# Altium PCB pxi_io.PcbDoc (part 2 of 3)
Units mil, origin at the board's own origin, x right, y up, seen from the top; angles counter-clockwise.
Board outline 6300 x 3935 mil, 2 copper layers (Top Layer, Bottom Layer); 257 components, 420 nets, 1532 pads, 239 vias.
Unrouted connection lines stored in the file: 158.
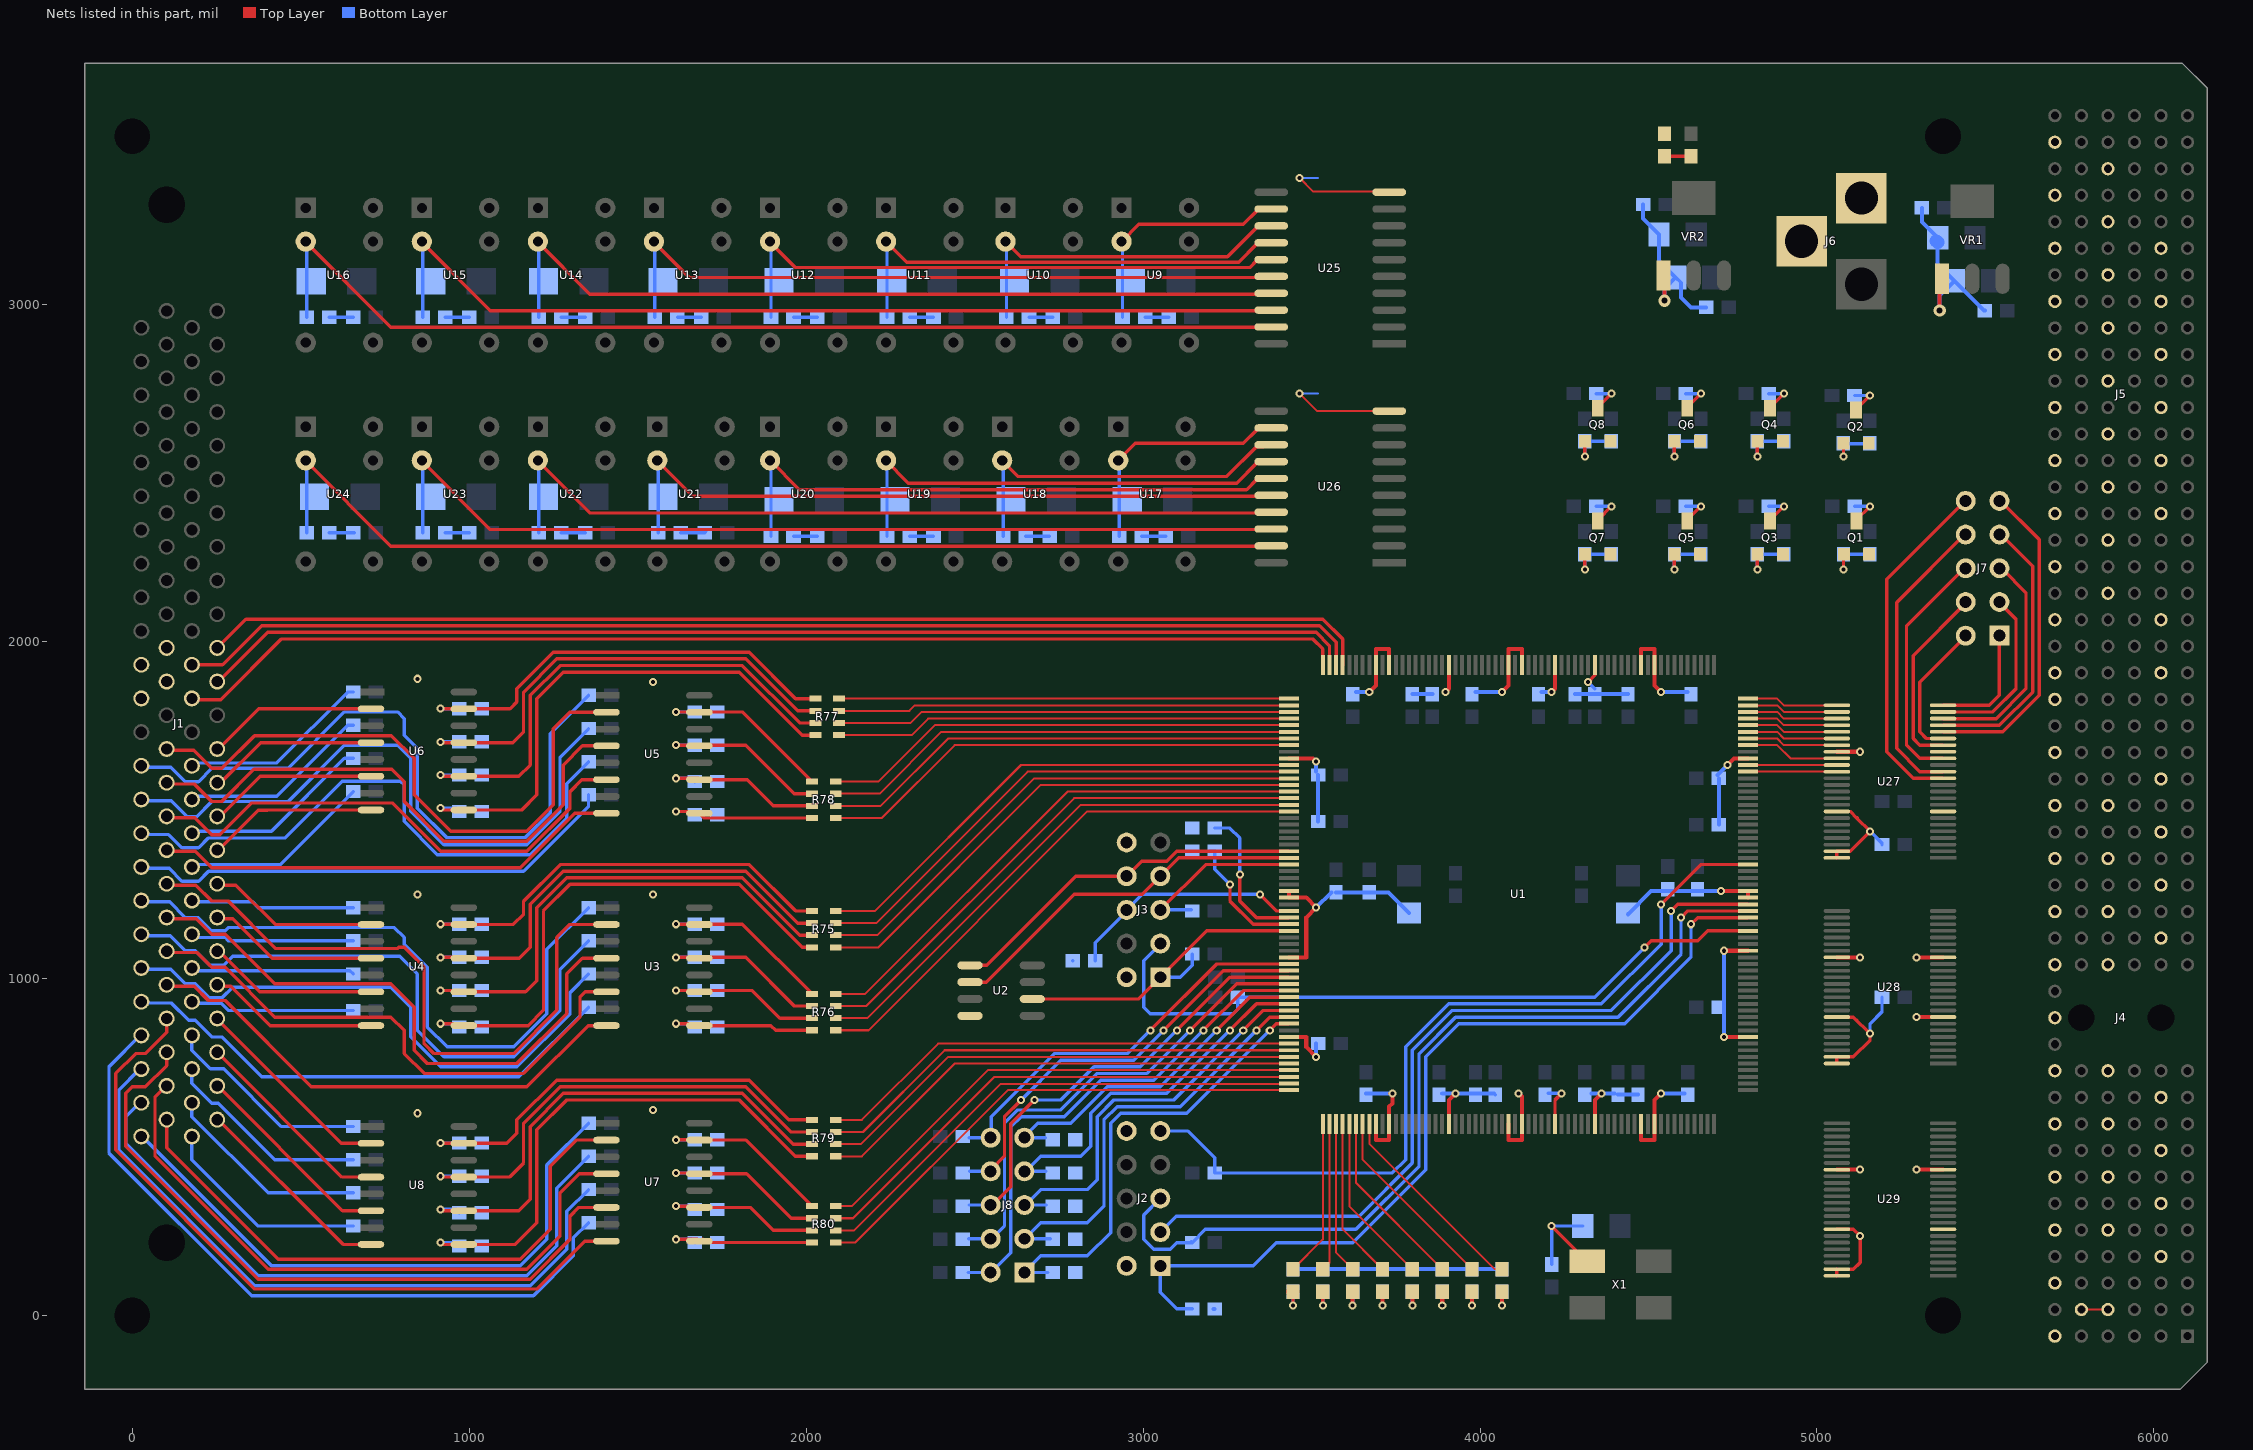
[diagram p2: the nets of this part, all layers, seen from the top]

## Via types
v1: diameter 24, hole 12, Top Layer to Bottom Layer, 232 vias
v2: diameter 36, hole 18, Top Layer to Bottom Layer, 6 vias
v3: diameter 24, hole 12, Top Layer to Bottom Layer, tented bottom, 1 vias

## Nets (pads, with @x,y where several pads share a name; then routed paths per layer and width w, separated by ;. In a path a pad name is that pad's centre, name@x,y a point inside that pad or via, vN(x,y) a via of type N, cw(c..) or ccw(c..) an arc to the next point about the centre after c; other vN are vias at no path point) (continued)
CONF_DONE: J3.3 R6.2 U1.145 | length 2131.5
  Top Layer w10: v1(4488.19,1092.52) 4507.87,1112.2 4645.67,1112.2 4675.2,1141.73 U1.145@4795.28,1141.73
  Bottom Layer w10: J3.3@3051.18,1102.36 3001.97,1053.15 3001.97,915.35 3021.65,895.67 3267.72,895.67 3281.5,909.45 R6.2@3281.5,944.88 4340.55,944.88 v1(4488.19,1092.52)
CTRL_RES1: J1.29 U1.238 | length 3532.9
  Top Layer w10: J1.29@177.17,1931.5 268.11,1931.5 383.86,2047.24 3523.62,2047.24 3572.83,1998.03 U1.238@3572.83,1931.1 U1.238@3572.83,1929.13
CTRL_RES2: J1.30 U1.237 | length 3478.9
  Top Layer w10: J1.30@252.17,1981.5 337.6,2066.93 3533.46,2066.93 3592.52,2007.87 U1.237@3592.52,1929.13
CTRL_V5: J1.27 U1.240 | length 3492.4
  Top Layer w10: J1.27@177.17,1827.56 262.6,1827.56 442.91,2007.87 3503.94,2007.87 3533.46,1978.35 U1.240@3533.46,1929.13
CTRL_V27: J1.28 U1.239 | length 3428.6
  Top Layer w10: J1.28@252.17,1877.56 402.17,2027.56 3513.78,2027.56 3553.15,1988.19 U1.239@3553.15,1938.98
DATA: J3.7 U1.25 U2.2 | length 1077.7
  Top Layer w10: U2.2@2515.75,989.57 2534.84,989.57 2795.28,1250 2997.24,1250 J3.7@3051.18,1303.94 ; J3.7@3058.85,1303.94 J3.7@3051.18,1303.94 ; U1.25@3433.07,1358.27 3105.51,1358.27 J3.7@3051.18,1303.94
DCLK: J3.1 R5.2 U1.36 U2.6 | length 958.7
  Top Layer w10: U2.6@2700.79,939.57 2986.81,939.57 J3.1@3051.18,1003.94 3188.98,1141.73 U1.36@3433.07,1141.73
  Bottom Layer w10: J3.1@3051.18,1003.94 3110.24,1003.94 3145.67,1039.37 R5.2@3145.67,1072.83
GND: C1.2 C2.1 C3.2 C5.1 C6.1 C7.2 C9.1 C10.1 C11.1 C12.1 C13.1 C14.1 C15.1 C16.1 C17.1 C18.1 C19.1 C20.1 C21.1 C22.1 C31.1 C32.1 C33.1 C34.1 C35.1 C36.1 C37.1 C38.1 C39.1 C40.1 C41.1 C42.1 C111.2 C112.1 C113.2 C114.1 C115.2 C116.1 C117.2 C118.1 C121.1 J1.77 J1.78 J1.79 J1.80 J2.2 J2.10 J3.2 J3.10 J4.B4 J4.B6 J4.B8 J4.B10 J4.B16 J4.B18 J4.B20 J4.B22 J4.D5 J4.D7 J4.D9 J4.D11 J4.D15 J4.D17 J4.D19 J4.D21 J4.F1 J4.F3 J4.F5 J4.F7 J4.F9 J4.F11 J4.F13 J4.F15 J4.F17 J4.F19 J4.F21 J4.F23 J4.F25 J5.B1 J5.B3 J5.B7 J5.B9 J5.B11 J5.B13 J5.B15 J5.B17 J5.D4 J5.D6 J5.D8 J5.D10 J5.D12 J5.D14 J5.D16 J5.D18 J5.D20 J5.F1 J5.F3 J5.F5 J5.F7 J5.F9 J5.F11 J5.F13 J5.F15 J5.F17 J5.F19 J5.F21 J6.2 J6.3 Q1.3 Q2.3 Q3.3 Q4.3 Q5.3 Q6.3 Q7.3 Q8.3 R3.2 R4.1 R9.2 R10.2 R15.2 R16.2 R17.2 R18.2 R23.2 R24.2 R25.2 R26.2 R31.2 R32.2 R33.2 R34.2 R39.2 R40.2 R41.2 R42.2 R55.2 R56.2 R57.2 R58.2 R71.2 R72.2 R73.2 R74.2 R116.1 R120.2 R121.2 R122.2 R123.2 R124.2 R125.2 R126.2 R127.2 R135.1 R136.1 R137.1 R138.1 R139.1 R200.1 U1.10 U1.30 U1.31 U1.40 U1.52 U1.69 U1.71 U1.80 U1.89 U1.91 U1.96 U1.102 U1.109 U1.111 U1.129 U1.142 U1.150 U1.151 U1.171 U1.190 U1.192 U1.199 U1.205 U1.210 U1.212 U1.221 U1.230 U1.232 U2.4 U25.10 U26.10 U27.8 U27.17 U27.32 U27.41 U27.47 U27.48 U28.8 U28.17 U28.32 U28.41 U28.47 U28.48 U29.8 U29.17 U29.32 U29.41 U29.47 U29.48 VR1.1 VR2.1 X1.2 | length 9085.3
  Top Layer w6: v1(3464.57,2736.22) 3516.54,2684.25 U26.10@3730.31,2684.25 ; v1(3464.57,3375.98) 3503.94,3336.61 U25.10@3730.31,3336.61
  Top Layer w10: v1(4212.6,265.75) 4317.24,161.1 X1.2@4318.13,161.1 ; U1.96@4222.44,568.9 4222.44,639.76 v1(4242.13,659.45) ; v1(4320.87,1879.92) 4340.55,1899.61 U1.199@4340.55,1931.1 ; U29.48@5059.06,118.11 U29.47@5059.06,137.8 ; U29.41@5059.06,255.91 5108.27,255.91 v1(5127.95,236.22) 5127.95,157.48 5108.27,137.8 5098.43,137.8 ; U28.48@5059.06,748.03 U28.47@5059.06,767.72 5108.27,767.72 5157.48,816.93 v1(5157.48,836.61) 5108.27,885.83 U28.41@5059.06,885.83 ; U27.48@5059.06,1358.27 U27.47@5059.06,1377.95 5098.43,1377.95 v1(5157.48,1437.01) 5118.11,1476.38 ; U27.41@5059.06,1496.06 5098.43,1496.06 5118.11,1476.38 ; 5119.08,1477.35 5118.11,1476.38
  Top Layer w12: U1.52@3433.07,826.77 3484.25,826.77 3484.25,797.24 v1(3513.78,767.72) ; U1.40@3433.07,1062.99 3484.25,1062.99 3484.25,1181.1 v1(3513.78,1210.63) 3484.25,1240.16 U1.31@3433.07,1240.16 U1.30@3433.07,1259.84 ; U1.10@3433.07,1653.54 3503.94,1653.54 v1(3513.78,1643.7) ; v1(3671.26,1850.39) 3690.94,1870.08 U1.232@3690.94,1931.1 3690.94,1978.35 3730.31,1978.35 U1.230@3730.31,1931.1 ; U1.69@3690.94,568.9 3690.94,521.65 3730.31,521.65 U1.71@3730.31,568.9 3730.31,620.08 3740.16,629.92 v1(3740.16,659.45) ; v1(3897.64,1850.39) 3907.48,1860.24 U1.221@3907.48,1931.1 ; U1.80@3907.48,568.9 3907.48,639.76 v1(3927.17,659.45) ; v1(4064.96,1850.39) 4084.65,1870.08 U1.212@4084.65,1931.1 4084.65,1978.35 4124.02,1978.35 U1.210@4124.02,1931.1 ; U1.89@4084.65,568.9 4084.65,521.65 4124.02,521.65 U1.91@4124.02,568.9 4124.02,649.61 v1(4114.17,659.45) ; v1(4212.6,1850.39) 4222.44,1860.24 U1.205@4222.44,1931.1 ; U1.102@4340.55,568.9 4340.55,639.76 v1(4360.24,659.45) ; U1.109@4478.35,568.9 4478.35,521.65 4517.72,521.65 U1.111@4517.72,568.9 4517.72,639.76 v1(4537.4,659.45) ; U1.192@4478.35,1931.1 4478.35,1978.35 4517.72,1978.35 U1.190@4517.72,1931.1 4517.72,1870.08 v1(4537.4,1850.39) ; v2(4547.24,3011.81) VR2.1@4547.24,3051.18 ; v1(4714.57,1259.84) U1.151@4795.28,1259.84 U1.150@4795.28,1240.16 ; v1(4724.41,826.77) U1.129@4795.28,826.77 ; v1(4724.41,1082.68) U1.142@4795.28,1082.68 ; v1(4734.25,1633.86) 4753.94,1653.54 U1.171@4795.28,1653.54 ; U29.32@5059.06,433.07 v1(5127.95,433.07) ; U28.32@5059.06,1062.99 v1(5127.95,1062.99) ; U27.32@5059.06,1673.23 v1(5127.95,1673.23) ; v1(5295.28,433.07) U29.17@5374.02,433.07 ; v1(5295.28,885.83) U28.8@5374.02,885.83 ; v1(5295.28,1062.99) U28.17@5374.02,1062.99 ; v2(5364.17,2982.28) VR1.1@5364.17,3070.13
  Bottom Layer w6: v1(3464.57,2736.22) 3519.69,2736.22 ; v1(3464.57,3375.98) 3519.69,3375.98
  Bottom Layer w10: C18.1@4041.34,659.45 C18.1@4045.28,655.51 ; C38.1@4202.76,659.45 v1(4242.13,659.45) ; C2.1@4212.6,151.57 v1(4212.6,265.75) C1.2@4305.12,265.75 ; v1(4320.87,1879.92) C15.1@4340.55,1860.24 ; C115.2@4580.71,3080.71 C115.2@4596.46,3064.96 ; v1@5157.48,832.68 v1(5157.48,836.61) 5157.48,866.14 5192.91,901.57 C121.1@5192.91,944.88 ; v1(5157.48,1437.01) 5192.91,1401.57 R116.1@5192.91,1397.64 ; C111.2@5407.48,3070.87 C111.2@5423.23,3055.12
  Bottom Layer w12: R3.2@3208.66,19.68 R3.2@3212.6,19.68 ; R127.2@3444.88,137.8 R126.2@3533.46,137.8 R125.2@3622.05,137.8 R124.2@3710.63,137.8 R123.2@3799.21,137.8 R122.2@3887.8,137.8 R121.2@3976.38,137.8 R120.2@4064.96,137.8 ; v1(3513.78,767.72) C40.1@3513.78,807.09 ; v1(3513.78,1210.63) C6.1@3559.06,1255.91 ; C42.1@3513.78,1614.17 v1(3513.78,1643.7) ; C41.1@3519.69,1466.54 C42.1@3519.69,1604.33 ; C6.1@3572.83,1255.91 C5.1@3671.26,1255.91 3728.35,1255.91 C3.2@3789.37,1194.88 ; C31.1@3631.89,1850.39 v1(3671.26,1850.39) ; C39.1@3661.42,659.45 v1(3740.16,659.45) ; C11.1@3799.21,1844.49 C12.1@3858.27,1844.49 ; C17.1@3887.8,659.45 v1(3927.17,659.45) C18.1@4041.34,659.45 ; C13.1@3986.22,1850.39 v1(4064.96,1850.39) ; C32.1@4183.07,1850.39 v1(4212.6,1850.39) ; C14.1@4281.5,1844.49 C15.1@4340.55,1844.49 C16.1@4438.98,1844.49 ; 4330.71,659.45 v1(4360.24,659.45) C21.1@4399.61,659.45 ; C21.1@4409.45,655.51 C22.1@4468.5,655.51 ; C7.2@4438.98,1190.94 4507.87,1259.84 v1(4714.57,1259.84) ; C118.1@4484.25,3297.24 4484.25,3255.91 C117.2@4531.5,3208.66 4531.5,3129.92 C115.2@4580.71,3080.71 4547.24,3047.24 v2(4547.24,3011.81) ; v1(4537.4,659.45) C37.1@4606.3,659.45 ; v1(4537.4,1850.39) C33.1@4616.14,1850.39 ; C115.2@4596.46,3064.96 4596.46,3021.65 4625.98,2992.13 C116.1@4671.26,2992.13 ; C34.1@4704.72,1604.33 v1(4734.25,1633.86) ; C35.1@4708.66,1456.69 C34.1@4708.66,1594.49 ; v1(4724.41,826.77) 4724.41,905.51 v1(4724.41,1082.68) ; C114.1@5311.02,3287.4 5311.02,3246.06 C113.2@5358.27,3198.82 ; C113.2@5358.27,3185.04 5358.27,3120.08 C111.2@5407.48,3070.87 ; v2(5364.17,2982.28) 5364.17,3027.56 C111.2@5407.48,3070.87 ; C112.1@5498.03,2982.28 5496.06,2982.28 C111.2@5407.48,3070.87
  Bottom Layer w40: C113.2@5354.33,3188.98 C113.2@5358.27,3185.04
  other v1: 846.46,600.39 1545.28,610.24 846.46,1250 1545.28,1250 1545.28,1879.92 846.46,1889.76
GND_I5_1: J1.60 U3.8 | length 1504.1
  Top Layer w10: J1.60@102.17,977.56 183.86,977.56 226.38,935.04 275.59,935.04 531.5,679.13 1171.26,679.13 1352.76,860.63 U3.8@1407.48,860.63
GND_I5_2: J1.62 U3.6 | length 1629.3
  Top Layer w10: J1.62@102.17,1077.56 192.13,1077.56 236.22,1033.46 275.59,1033.46 423.23,885.83 767.72,885.83 807.09,846.46 807.09,777.56 866.14,718.5 1161.42,718.5 1328.74,885.83 1328.74,944.88 1344.49,960.63 U3.6@1407.48,960.63
GND_I5_3: J1.64 U3.4 | length 1756.9
  Top Layer w10: J1.64@102.17,1177.56 190.55,1177.56 236.22,1131.89 275.59,1131.89 423.23,984.25 767.72,984.25 836.61,915.35 836.61,787.4 875.98,748.03 1141.73,748.03 1289.37,895.67 1289.37,1013.78 1336.22,1060.63 U3.4@1407.48,1060.63
GND_I5_4: J1.66 U3.2 | length 1933.3
  Top Layer w10: J1.66@102.17,1277.56 188.98,1277.56 236.22,1230.32 285.43,1230.32 426.54,1089.2 787.09,1089.2 790.4,1092.52 807.09,1092.52 866.14,1033.46 866.14,807.09 895.67,777.56 1131.89,777.56 1259.84,905.51 1259.84,1122.05 1298.43,1160.63 U3.2@1407.48,1160.63
GND_I5_5: J1.10 U4.8 | length 504.9
  Top Layer w10: J1.10@252.17,977.56 292.13,977.56 409.05,860.63 U4.8@708.66,860.63
GND_I5_6: J1.12 U4.6 | length 502.3
  Top Layer w10: J1.12@256.59,1081.99 377.95,960.63 U4.6@708.66,960.63
GND_I5_7: J1.14 U4.4 | length 504.9
  Top Layer w10: J1.14@252.17,1177.56 298.82,1177.56 415.75,1060.63 U4.4@708.66,1060.63
GND_I5_8: J1.16 U4.2 | length 504.9
  Top Layer w10: J1.16@252.17,1277.56 307.09,1277.56 424.02,1160.63 U4.2@708.66,1160.63
GND_I5_9: J1.68 U5.8 | length 1392.6
  Top Layer w10: J1.68@102.17,1377.56 187.4,1377.56 236.22,1328.74 1151.57,1328.74 1313.39,1490.55 U5.8@1407.48,1490.55
GND_I5_10: J1.70 U5.6 | length 1541.4
  Top Layer w10: J1.70@102.17,1477.56 185.83,1477.56 236.22,1427.17 260.26,1427.17 354.33,1521.24 772.07,1521.24 915.35,1377.95 1171.26,1377.95 1299.21,1505.91 1299.21,1555.12 1334.65,1590.55 U5.6@1407.48,1590.55
GND_I5_11: J1.72 U5.4 | length 1676
  Top Layer w10: J1.72@102.17,1577.56 184.25,1577.56 236.22,1525.59 265.75,1525.59 361.39,1621.24 770.5,1621.24 807.09,1584.65 807.09,1525.59 925.2,1407.48 1171.26,1407.48 1279.53,1515.75 1279.53,1633.86 1336.22,1690.55 U5.4@1407.48,1690.55
GND_I5_12: J1.74 U5.2 | length 1828
  Top Layer w10: J1.74@102.17,1677.56 182.68,1677.56 236.22,1624.02 265.75,1624.02 362.97,1721.24 768.92,1721.24 836.61,1653.54 836.61,1545.28 944.88,1437.01 1171.26,1437.01 1250,1515.75 1250,1742.13 1298.43,1790.55 U5.2@1407.48,1790.55
GND_I5_13: J1.18 U6.8 | length 507.4
  Top Layer w10: J1.18@252.17,1377.56 374.35,1499.75 400.33,1499.75 400.97,1500.39 U6.8@708.66,1500.39
GND_I5_14: J1.20 U6.6 | length 508.8
  Top Layer w10: J1.20@249.7,1480.02 259.55,1480.02 379.92,1600.39 U6.6@708.66,1600.39
GND_I5_15: J1.22 U6.4 | length 500.9
  Top Layer w10: J1.22@258.66,1577.56 381.5,1700.39 U6.4@708.66,1700.39
GND_I5_16: J1.24 U6.2 | length 507.4
  Top Layer w10: J1.24@252.17,1677.56 375,1800.39 U6.2@708.66,1800.39
GND_I27_1: J1.58 U7.8 | length 2152.2
  Top Layer w10: J1.58@102.17,877.56 102.17,840.35 39.37,777.56 9.84,777.56 -49.21,718.5 -49.21,492.13 364.17,78.74 1200.79,78.74 1342.91,220.87 U7.8@1407.48,220.87
GND_I27_2: J1.56 U7.6 | length 2067.8
  Top Layer w10: J1.56@102.17,777.56 102.17,741.93 39.37,679.13 0,679.13 -19.68,659.45 -19.68,501.97 374.02,108.27 1181.1,108.27 1299.21,226.38 1299.21,295.28 1324.8,320.87 U7.6@1407.48,320.87
GND_I27_3: J1.54 U7.4 | length 1894.7
  Top Layer w10: J1.54@102.17,682.87 67.54,648.25 67.54,473.8 403.54,137.8 1171.26,137.8 1269.68,236.22 1269.68,364.17 1326.38,420.87 U7.4@1407.48,420.87
GND_I27_4: J1.52 U7.2 | length 1777.7
  Top Layer w10: J1.52@102.17,577.56 102.17,498.23 433.07,167.32 1151.57,167.32 1240.16,255.91 1240.16,442.91 1318.11,520.87 U7.2@1407.48,520.87
GND_I27_5: J1.2 U8.8 | length 611.2
  Top Layer w10: J1.2@252.17,584.45 625.59,211.02 U8.8@708.66,211.02
GND_I27_6: J1.4 U8.6 | length 610.5
  Top Layer w10: J1.4@252.17,682.87 624.02,311.02 U8.6@708.66,311.02
GND_I27_7: J1.6 U8.4 | length 609.9
  Top Layer w10: J1.6@252.17,781.3 622.44,411.02 U8.4@708.66,411.02
GND_I27_8: J1.8 U8.2 | length 609.2
  Top Layer w10: J1.8@252.17,879.72 620.87,511.02 U8.2@708.66,511.02
I5_1: J1.59 R11.1 | length 1503.5
  Bottom Layer w10: J1.59@27.17,927.56 115.75,927.56 167.32,875.98 187.01,875.98 236.22,826.77 265.75,826.77 383.86,708.66 1147.64,708.66 R11.1@1354.33,915.35
I5_2: J1.61 R12.1 | length 1676
  Bottom Layer w10: J1.61@27.17,1027.56 114.17,1027.56 157.48,984.25 187.01,984.25 228.32,942.94 266.51,942.94 297.98,974.41 767.72,974.41 826.77,915.35 826.77,826.77 915.35,738.19 1141.73,738.19 1299.21,895.67 1299.21,958.66 R12.1@1354.33,1013.78
I5_3: J1.63 R13.1 | length 1810.7
  Bottom Layer w10: J1.63@27.17,1127.56 112.6,1127.56 157.48,1082.68 187.01,1082.68 230.06,1039.62 271.91,1039.62 298.84,1066.56 793.68,1066.56 846.46,1013.78 846.46,846.46 925.2,767.72 1131.89,767.72 1269.68,905.51 1269.68,1027.56 R13.1@1354.33,1112.2
I5_4: J1.65 R14.1 | length 1912
  Bottom Layer w10: J1.65@27.17,1227.56 111.02,1227.56 157.48,1181.1 195.46,1181.1 234.83,1141.73 275.59,1141.73 285.43,1151.57 777.56,1151.57 807.09,1122.05 807.09,1102.36 875.98,1033.46 875.98,856.3 935.04,797.24 1131.89,797.24 1230.32,895.67 1230.32,1086.61 R14.1@1354.33,1210.63
I5_5: J1.9 R19.1 | length 487.5
  Bottom Layer w10: J1.9@177.17,927.56 177.79,926.94 264.01,926.94 285.43,905.51 R19.1@655.51,905.51
I5_6: J1.11 R20.1 | length 483.3
  Bottom Layer w10: J1.11@177.17,1023.62 645.67,1023.62 R20.1@655.51,1013.78 ; J1.11@177.17,1027.56 J1.11@177.79,1026.94
I5_7: J1.13 R21.1 | length 484.7
  Bottom Layer w10: J1.13@177.17,1127.56 182.68,1122.05 275.59,1122.05 285.43,1112.2 R21.1@655.51,1112.2
I5_8: J1.15 R22.1 | length 485.4
  Bottom Layer w10: J1.15@177.17,1227.56 357.09,1227.56 374.02,1210.63 R22.1@655.51,1210.63
I5_9: J1.67 R27.1 | length 1468.6
  Bottom Layer w10: J1.67@27.17,1327.56 109.45,1327.56 147.64,1289.37 196.85,1289.37 226.38,1318.9 1161.42,1318.9 1354.33,1511.81 R27.1@1354.33,1545.28
I5_10: J1.69 R28.1 | length 1753.4
  Bottom Layer w10: J1.69@27.17,1427.56 107.87,1427.56 147.64,1387.8 196.85,1387.8 226.38,1417.32 454.38,1417.32 622.86,1585.8 796.09,1585.8 807.09,1574.8 807.09,1466.54 905.51,1368.11 1181.1,1368.11 1289.37,1476.38 1289.37,1578.74 R28.1@1354.33,1643.7
I5_11: J1.71 R29.1 | length 1886.3
  Bottom Layer w10: J1.71@27.17,1527.56 116.14,1527.56 163.02,1480.68 191.31,1480.68 236.22,1525.59 462.6,1525.59 629.92,1692.91 787.4,1692.91 826.77,1653.54 826.77,1496.06 925.2,1397.64 1171.26,1397.64 1269.68,1496.06 1269.68,1657.48 R29.1@1354.33,1742.13
I5_12: J1.73 R30.1 | length 2029.2
  Bottom Layer w10: J1.73@27.17,1627.56 114.57,1627.56 157.48,1584.65 196.85,1584.65 236.22,1624.02 462.6,1624.02 629.92,1791.34 787.4,1791.34 807.09,1771.65 807.09,1722.44 846.46,1683.07 846.46,1505.91 933.57,1418.79 1166.57,1418.79 1240.16,1492.38 1240.16,1726.38 R30.1@1354.33,1840.55
I5_13: J1.17 R35.1 | length 555.4
  Bottom Layer w10: J1.17@189.76,1338.58 438.98,1338.58 R35.1@655.51,1555.12
I5_14: J1.19 R36.1 | length 572
  Bottom Layer w10: J1.19@177.17,1427.56 186.61,1437.01 413.39,1437.01 629.92,1653.54 R36.1@655.51,1653.54
I5_15: J1.21 R37.1 | length 554.3
  Bottom Layer w10: J1.21@190.94,1535.43 197.1,1541.59 429.39,1541.59 639.76,1751.97 R37.1@655.51,1751.97
I5_16: J1.23 R38.1 | length 570.6
  Bottom Layer w10: J1.23@177.17,1627.56 189.62,1640.02 429.39,1640.02 639.76,1850.39 R38.1@655.51,1850.39
I5_D1: R76.5 U1.18 | length 1614.2
  Top Layer w6: R76.5@2087.87,846.72 2185.31,846.72 2834.65,1496.06 U1.18@3433.07,1496.06
I5_D1_R: R15.1 R76.4 U3.9 | length 470.6
  Top Layer w10: v1(1614.17,866.14) 1677.56,866.14 U3.9@1683.07,860.63 1895.28,860.63 1909.18,846.72 R76.4@2017.72,846.72
  Bottom Layer w10: v1(1614.17,866.14) R15.1@1673.23,866.14
I5_D2: R76.6 U1.17 | length 1607.4
  Top Layer w6: R76.6@2087.87,882.72 2181.94,882.72 2814.96,1515.75 U1.17@3433.07,1515.75
I5_D2_R: R16.1 R76.3 U3.11 | length 492.6
  Top Layer w10: v1(1614.17,964.57) 1683.07,964.57 1840.55,964.57 1922.39,882.72 R76.3@2017.72,882.72
  Bottom Layer w10: v1(1614.17,964.57) R16.1@1669.29,964.57
I5_D3: R76.7 U1.16 | length 1600.6
  Top Layer w6: R76.7@2087.87,918.72 2178.57,918.72 2795.28,1535.43 U1.16@3433.07,1535.43
I5_D3_R: R17.1 R76.2 U3.13 | length 521.8
  Top Layer w10: v1(1614.17,1062.99) U3.13@1680.71,1062.99 ; U3.13@1683.07,1060.63 U3.13@1680.71,1062.99 ; R76.2@2017.72,918.72 1965.13,918.72 1820.87,1062.99 U3.13@1680.71,1062.99
  Bottom Layer w10: v1(1614.17,1062.99) R17.1@1669.29,1062.99
I5_D4: R76.8 U1.15 | length 1593.9
  Top Layer w6: R76.8@2087.87,954.72 2175.2,954.72 2775.59,1555.12 U1.15@3433.07,1555.12
I5_D4_R: R18.1 R76.1 U3.15 | length 545.4
  Top Layer w10: v1(1614.17,1161.42) U3.15@1682.28,1161.42 ; U3.15@1683.07,1160.63 U3.15@1682.28,1161.42 ; R76.1@2017.72,954.72 1811.02,1161.42 U3.15@1682.28,1161.42
  Bottom Layer w10: v1(1614.17,1161.42) R18.1@1669.29,1161.42
I5_D5: R75.5 U1.14 | length 1544.9
  Top Layer w6: R75.5@2087.87,1092.79 2214.83,1092.79 2696.85,1574.8 U1.14@3433.07,1574.8
I5_D5_R: R23.1 R75.4 U4.9 | length 1575.5
  Top Layer w10: v1(915.35,866.14) U4.9@974.41,866.14 ; U4.9@984.25,860.63 1175.59,860.63 1220.47,905.51 1220.47,1200.79 1299.21,1279.53 1801.18,1279.53 1987.92,1092.79 R75.4@2017.72,1092.79
  Bottom Layer w10: v1(915.35,866.14) 960.63,866.14 R23.1@970.47,856.3
I5_D6: R75.6 U1.13 | length 1538.1
  Top Layer w6: R75.6@2087.87,1128.79 2211.46,1128.79 2677.17,1594.49 U1.13@3433.07,1594.49
I5_D6_R: R24.1 R75.3 U4.11 | length 1496.8
  Top Layer w10: v1(915.35,964.57) 980.32,964.57 U4.11@984.25,960.63 1167.32,960.63 1200.79,994.09 1200.79,1210.63 1289.37,1299.21 1811.02,1299.21 1981.45,1128.79 R75.3@2017.72,1128.79
  Bottom Layer w10: v1(915.35,964.57) R24.1@970.47,964.57
I5_D7: R75.7 U1.12 | length 1531.3
  Top Layer w6: R75.7@2087.87,1164.79 2208.09,1164.79 2657.48,1614.17 U1.12@3433.07,1614.17
I5_D7_R: R25.1 R75.2 U4.13 | length 1404.2
  Top Layer w10: v1(915.35,1062.99) 981.89,1062.99 U4.13@984.25,1060.63 1149.21,1060.63 1181.1,1092.52 1181.1,1220.47 1279.53,1318.9 1820.87,1318.9 1974.98,1164.79 R75.2@2017.72,1164.79
  Bottom Layer w10: v1(915.35,1062.99) R25.1@970.47,1062.99
I5_D8: R75.8 U1.11 | length 1524.6
  Top Layer w6: R75.8@2087.87,1200.79 2204.72,1200.79 2637.8,1633.86 U1.11@3433.07,1633.86
I5_D8_R: R26.1 R75.1 U4.15 | length 1311.7
  Top Layer w10: v1(915.35,1161.42) 983.46,1161.42 U4.15@984.25,1160.63 1131.1,1160.63 1161.42,1190.94 1161.42,1230.31 1269.69,1338.58 1830.71,1338.58 1968.5,1200.79 R75.1@2017.72,1200.79
  Bottom Layer w10: v1(915.35,1161.42) R26.1@970.47,1161.42
I5_D9: R78.5 U1.8 | length 1434.8
  Top Layer w6: R78.5@2087.87,1476.65 2224.68,1476.65 2440.94,1692.91 U1.8@3433.07,1692.91
I5_D9_R: R31.1 R78.4 U5.9 | length 456.9
  Top Layer w10: v1(1614.17,1496.06) 1677.56,1496.06 U5.9@1683.07,1490.55 1696.98,1476.65 R78.4@2017.72,1476.65
  Bottom Layer w10: v1(1614.17,1496.06) R31.1@1659.45,1496.06
I5_D10: R78.6 U1.7 | length 1428
  Top Layer w6: R78.6@2087.87,1512.65 2221.31,1512.65 2421.26,1712.6 U1.7@3433.07,1712.6
I5_D10_R: R32.1 R78.3 U5.11 | length 496.6
  Top Layer w10: v1(1614.17,1594.49) 1679.13,1594.49 U5.11@1683.07,1590.55 1824.8,1590.55 1902.71,1512.65 R78.3@2017.72,1512.65
  Bottom Layer w10: v1(1614.17,1594.49) 1659.45,1594.49 R32.1@1669.29,1584.65
I5_D11: R78.7 U1.6 | length 1421.3
  Top Layer w6: R78.7@2087.87,1548.65 2217.94,1548.65 2401.57,1732.28 U1.6@3433.07,1732.28
I5_D11_R: R33.1 R78.2 U5.13 | length 521.8
  Top Layer w10: v1(1614.17,1692.91) U5.13@1680.71,1692.91 ; U5.13@1683.07,1690.55 U5.13@1680.71,1692.91 ; R78.2@2017.72,1548.65 1965.13,1548.65 1820.87,1692.91 U5.13@1680.71,1692.91
  Bottom Layer w10: v1(1614.17,1692.91) R33.1@1669.29,1692.91
I5_D12: R78.8 U1.5 | length 1414.5
  Top Layer w6: R78.8@2087.87,1584.65 2214.57,1584.65 2381.89,1751.97 U1.5@3433.07,1751.97
I5_D12_R: R34.1 R78.1 U5.15 | length 545.4
  Top Layer w10: v1(1614.17,1791.34) U5.15@1682.28,1791.34 ; U5.15@1683.07,1790.55 U5.15@1682.28,1791.34 ; R78.1@2017.72,1584.65 1811.02,1791.34 U5.15@1682.28,1791.34
  Bottom Layer w10: v1(1614.17,1791.34) R34.1@1669.29,1791.34
I5_D13: R77.5 U1.4 | length 1365.5
  Top Layer w6: R77.5@2087.87,1722.71 2313.26,1722.71 2362.2,1771.65 U1.4@3433.07,1771.65
I5_D13_R: R39.1 R77.4 U6.9 | length 1577.9
  Top Layer w10: v1(915.35,1505.91) 920.87,1500.39 U6.9@984.25,1500.39 1155.91,1500.39 1200.79,1545.28 1200.79,1830.71 1279.53,1909.45 1801.18,1909.45 1988.19,1722.44 R77.4@2017.72,1722.44
  Bottom Layer w10: v1(915.35,1505.91) 960.63,1505.91 R39.1@970.47,1496.06
I5_D14: R77.6 U1.3 | length 1358.7
  Top Layer w6: R77.6@2087.87,1758.71 2309.89,1758.71 2342.52,1791.34 U1.3@3433.07,1791.34
I5_D14_R: R40.1 R77.3 U6.11 | length 1486.9
  Top Layer w10: v1(915.35,1604.33) 919.29,1600.39 U6.11@984.25,1600.39 1147.64,1600.39 1181.1,1633.86 1181.1,1840.55 1269.69,1929.13 1811.02,1929.13 1981.45,1758.71 R77.3@2017.72,1758.71
  Bottom Layer w10: v1(915.35,1604.33) R40.1@970.47,1604.33
I5_D15: R77.7 U1.2 | length 1352
  Top Layer w6: R77.7@2087.87,1794.71 2306.52,1794.71 2322.83,1811.02 U1.2@3433.07,1811.02
I5_D15_R: R41.1 R77.2 U6.13 | length 1394.4
  Top Layer w10: v1(915.35,1702.76) 917.72,1700.39 U6.13@984.25,1700.39 1129.53,1700.39 1161.42,1732.28 1161.42,1850.39 1259.84,1948.82 1820.87,1948.82 1974.98,1794.71 R77.2@2017.72,1794.71
  Bottom Layer w10: v1(915.35,1702.76) R41.1@970.47,1702.76
I5_D16: R77.8 U1.1 | length 1335.4
  Top Layer w6: R77.8@2097.72,1830.71 U1.1@3433.07,1830.71
I5_D16_R: R42.1 R77.1 U6.15 | length 1307.6
  Top Layer w10: v1(915.35,1801.18) 916.14,1800.39 U6.15@984.25,1800.39 1121.26,1800.39 1141.73,1820.87 1141.73,1860.24 1250,1968.5 1830.71,1968.5 1968.5,1830.71 R77.1@2017.72,1830.71
  Bottom Layer w10: v1(915.35,1801.18) R42.1@970.47,1801.18
I27_1: J1.57 R45.1 | length 2111.1
  Bottom Layer w10: J1.57@27.17,834.25 -68.9,738.19 -68.9,482.28 354.33,59.06 1190.94,59.06 1309.06,177.17 1309.06,230.31 R45.1@1354.33,275.59
I27_2: J1.55 R48.1 | length 2010.2
  Bottom Layer w10: J1.55@23.03,731.69 -39.37,669.29 -39.37,492.13 364.17,88.58 1181.1,88.58 1289.37,196.85 1289.37,309.06 R48.1@1354.33,374.02
I27_3: J1.53 R51.1 | length 1922.6
  Bottom Layer w10: J1.53@12.8,636.81 12.8,623.03 -19.68,590.55 -19.68,511.81 374.02,118.11 1171.26,118.11 1259.84,206.69 1259.84,377.95 R51.1@1354.33,472.44
I27_4: J1.51 R54.1 | length 1787.5
  Bottom Layer w10: J1.51@27.17,524.02 37.01,524.02 413.39,147.64 1151.57,147.64 1230.32,226.38 1230.32,446.85 R54.1@1354.33,570.87
I27_5: J1.1 R61.1 | length 624.8
  Bottom Layer w10: J1.1@177.17,527.56 177.17,462.6 374.02,265.75 R61.1@655.51,265.75
I27_6: J1.3 R64.1 | length 609.1
  Bottom Layer w10: J1.3@177.17,627.56 177.17,590.55 403.54,364.17 R64.1@655.51,364.17
I27_7: J1.5 R67.1 | length 610.7
  Bottom Layer w10: J1.5@177.17,727.56 177.17,688.98 236.22,629.92 255.91,629.92 423.23,462.6 R67.1@655.51,462.6
I27_8: J1.7 R70.1 | length 612.3
  Bottom Layer w10: J1.7@177.17,827.56 177.17,787.4 232.23,732.34 271.6,732.34 442.91,561.02 R70.1@655.51,561.02
I27_D1: R80.5 U1.60 | length 1532.6
  Top Layer w6: R80.5@2087.87,216.8 2145.94,216.8 2598.43,669.29 U1.60@3433.07,669.29
I27_D1_R: R55.1 R80.4 U7.9 | length 459.1
  Top Layer w10: v1(1614.17,226.38) 1677.56,226.38 U7.9@1683.07,220.87 ; U7.9@1692.91,226.38 1702.49,216.8 R80.4@2017.72,216.8
  Bottom Layer w10: v1(1614.17,226.38) 1659.45,226.38 R55.1@1669.29,216.54
I27_D2: R80.6 U1.59 | length 1525.9
  Top Layer w6: R80.6@2087.87,252.8 2142.57,252.8 2577.32,687.56 3431.65,687.56 U1.59@3433.07,688.98
I27_D2_R: R56.1 R80.3 U7.11 | length 492.6
  Top Layer w10: v1(1614.17,324.8) 1679.13,324.8 U7.11@1683.07,320.87 1834.65,320.87 1902.71,252.8 R80.3@2017.72,252.8
  Bottom Layer w10: v1(1614.17,324.8) 1659.45,324.8 R56.1@1669.29,314.96
I27_D3: R80.7 U1.58 | length 1519.1
  Top Layer w6: R80.7@2087.87,288.8 2139.2,288.8 2559.06,708.66 U1.58@3433.07,708.66
I27_D3_R: R57.1 R80.2 U7.13 | length 514.3
  Top Layer w10: v1(1614.17,423.23) 1680.71,423.23 U7.13@1683.07,420.87 1823.23,420.87 1955.29,288.8 R80.2@2017.72,288.8
  Bottom Layer w10: v1(1614.17,423.23) R57.1@1669.29,423.23
I27_D4: R80.8 U1.57 | length 1512.3
  Top Layer w6: R80.8@2087.87,324.8 2135.83,324.8 2539.37,728.35 U1.57@3433.07,728.35
I27_D4_R: R58.1 R80.1 U7.15 | length 540.2
  Top Layer w10: v1(1614.17,521.65) 1682.28,521.65 U7.15@1683.07,520.87 1821.65,520.87 R80.1@2017.72,324.8
  Bottom Layer w10: v1(1614.17,521.65) R58.1@1669.29,521.65
I27_D5: R79.5 U1.56 | length 1459.2
  Top Layer w6: R79.5@2087.87,472.71 2165.62,472.71 2440.94,748.03 U1.56@3433.07,748.03
I27_D5_R: R71.1 R79.4 U8.9 | length 1572.1
  Top Layer w10: v1(915.35,216.54) 920.87,211.02 U8.9@984.25,211.02 1136.22,211.02 1200.79,275.59 1200.79,551.18 1289.37,639.76 1801.18,639.76 1968.24,472.71 R79.4@2017.72,472.71
  Bottom Layer w10: v1(915.35,216.54) 960.63,216.54 R71.1@970.47,206.69
I27_D6: R79.6 U1.55 | length 1452.5
  Top Layer w6: R79.6@2087.87,508.71 2162.25,508.71 2421.26,767.72 U1.55@3433.07,767.72
I27_D6_R: R72.1 R79.3 U8.11 | length 1496.8
  Top Layer w10: v1(915.35,314.96) 919.29,311.02 U8.11@984.25,311.02 1147.64,311.02 1181.1,344.49 1181.1,561.02 1279.53,659.45 1811.02,659.45 1961.76,508.71 R79.3@2017.72,508.71
  Bottom Layer w10: v1(915.35,314.96) 960.63,314.96 R72.1@970.47,305.12
I27_D7: R79.7 U1.54 | length 1445.7
  Top Layer w6: R79.7@2087.87,544.71 2168.72,544.71 2411.42,787.4 U1.54@3433.07,787.4
I27_D7_R: R73.1 R79.2 U8.13 | length 1394.4
  Top Layer w10: v1(915.35,413.39) 917.72,411.02 U8.13@984.25,411.02 1119.68,411.02 1161.42,452.76 1161.42,570.87 1269.69,679.13 1820.87,679.13 1955.29,544.71 R79.2@2017.72,544.71
  Bottom Layer w10: v1(915.35,413.39) R73.1@970.47,413.39
I27_D8: R79.8 U1.53 | length 1439
  Top Layer w6: R79.8@2087.87,580.71 2165.35,580.71 2391.73,807.09 U1.53@3433.07,807.09
I27_D8_R: R74.1 R79.1 U8.15 | length 1307.6
  Top Layer w10: v1(915.35,511.81) 916.14,511.02 U8.15@984.25,511.02 1111.42,511.02 1141.73,541.34 1141.73,580.71 1259.84,698.82 1830.71,698.82 1948.82,580.71 R79.1@2017.72,580.71
  Bottom Layer w10: v1(915.35,511.81) R74.1@970.47,511.81
IO5_1: J7.1 U27.24 | length 356.7
  Top Layer w10: U27.24@5374.02,1811.02 5511.81,1811.02 5541.34,1840.55 J7.1@5541.34,2017.72
IO5_2: J7.2 U27.19 | length 419.6
  Top Layer w10: U27.19@5374.02,1712.6 5324.8,1712.6 5305.12,1732.28 5305.12,1879.92 J7.2@5442.91,2017.72
IO5_3: J7.3 U27.23 | length 521.4
  Top Layer w10: U27.23@5374.02,1791.34 5521.65,1791.34 5590.55,1860.24 5590.55,2066.93 J7.3@5541.34,2116.14
IO5_4: J7.4 U27.18 | length 565.5
  Top Layer w10: U27.18@5374.02,1692.91 5305.12,1692.91 5285.43,1712.6 5285.43,1958.66 J7.4@5442.91,2116.14
IO5_5: J7.5 U27.22 | length 665.6
  Top Layer w10: U27.22@5374.02,1771.65 5531.5,1771.65 5620.08,1860.24 5620.08,2145.67 J7.5@5551.18,2214.57
IO5_6: J7.6 U27.16 | length 729.5
  Top Layer w10: U27.16@5374.02,1653.54 5305.12,1653.54 5265.75,1692.91 5265.75,2047.24 J7.6@5442.91,2224.41
IO5_7: J7.7 U27.21 | length 819.7
  Top Layer w10: U27.21@5374.02,1751.97 5541.34,1751.97 5639.76,1850.39 5639.76,2224.41 J7.7@5541.34,2322.83
IO5_8: J7.8 U27.14 | length 891.7
  Top Layer w10: U27.14@5374.02,1614.17 5305.12,1614.17 5236.22,1683.07 5236.22,2116.14 J7.8@5442.91,2322.83
IO5_9: J7.9 U27.20 | length 959.9
  Top Layer w10: U27.20@5374.02,1732.28 5551.18,1732.28 5659.45,1840.55 5659.45,2303.15 J7.9@5541.34,2421.26
IO5_10: J7.10 U27.13 | length 1045.8
  Top Layer w10: U27.13@5374.02,1594.49 5285.43,1594.49 5206.69,1673.23 5206.69,2185.04 J7.10@5442.91,2421.26
IO5_D1: U1.180 U27.25 | length 271.9
  Top Layer w6: U1.180@4795.28,1830.71 4881.89,1830.71 4901.57,1811.02 U27.25@5059.06,1811.02
IO5_D2: U1.175 U27.30 | length 271.9
  Top Layer w6: U1.175@4795.28,1732.28 4881.89,1732.28 4901.57,1712.6 U27.30@5059.06,1712.6
IO5_D3: U1.179 U27.26 | length 271.9
  Top Layer w6: U1.179@4795.28,1811.02 4881.89,1811.02 4901.57,1791.34 U27.26@5059.06,1791.34
IO5_D4: U1.174 U27.31 | length 271.9
  Top Layer w6: U1.174@4795.28,1712.6 4881.89,1712.6 4901.57,1692.91 U27.31@5059.06,1692.91
IO5_D5: U1.178 U27.27 | length 271.9
  Top Layer w6: U1.178@4795.28,1791.34 4881.89,1791.34 4901.57,1771.65 U27.27@5059.06,1771.65
IO5_D6: U1.173 U27.33 | length 280.1
  Top Layer w6: U1.173@4795.28,1692.91 4881.89,1692.91 4921.26,1653.54 U27.33@5059.06,1653.54
IO5_D7: U1.177 U27.28 | length 271.9
  Top Layer w6: U1.177@4795.28,1771.65 4881.89,1771.65 4901.57,1751.97 U27.28@5059.06,1751.97
IO5_D8: U1.170 U27.34 | length 263.8
  Top Layer w6: U1.170@4795.28,1633.86 U27.34@5059.06,1633.86
IO5_D9: U1.176 U27.29 | length 271.9
  Top Layer w6: U1.176@4795.28,1751.97 4881.89,1751.97 4901.57,1732.28 U27.29@5059.06,1732.28
IO5_D10: U1.169 U27.35 | length 263.8
  Top Layer w6: U1.169@4795.28,1614.17 U27.35@5059.06,1614.17
IO_D1: J8.10 R130.1 U1.41 | length 1194.2
  Top Layer w10: v1(3021.65,846.46) 3218.5,1043.31 U1.41@3433.07,1043.31
  Bottom Layer w10: R130.1@2483.86,527.95 J8.10@2547.64,527.95 ; J8.10@2549.21,531.5 2549.21,590.55 2736.22,777.56 2952.76,777.56 v1(3021.65,846.46)
IO_D2: J8.9 R135.2 U1.46 | length 1019.3
  Top Layer w10: v1(3218.5,846.46) 3316.93,944.88 U1.46@3433.07,944.88
  Bottom Layer w10: J8.9@2647.64,527.95 2710.24,527.95 ; J8.9@2647.64,531.5 2687.01,570.87 2785.43,570.87 2893.7,679.13 3051.18,679.13 v1(3218.5,846.46)
IO_D3: J8.8 R131.1 U1.42 | length 1260.3
  Top Layer w10: J8.8@2549.21,433.07 2588.58,472.44 2588.58,590.55 v1(2637.8,639.76) ; v1(3061.02,846.46) 3238.19,1023.62 U1.42@3433.07,1023.62
  Bottom Layer w10: R131.1@2485.04,427.95 J8.8@2547.64,427.95 ; v1(2637.8,639.76) 2755.91,757.87 2972.44,757.87 v1(3061.02,846.46)
IO_D4: J8.7 R136.2 U1.47 | length 1115.2
  Top Layer w10: v1(3257.87,846.46) 3336.61,925.2 U1.47@3433.07,925.2
  Bottom Layer w10: J8.7@2647.64,423.23 J8.7@2652.36,427.95 ; J8.7@2647.64,427.95 J8.7@2652.36,427.95 ; R136.2@2711.81,427.95 J8.7@2652.36,427.95 ; v1(3257.87,846.46) 3070.87,659.45 2903.54,659.45 2844.49,600.39 2844.49,501.97 2814.96,472.44 2696.85,472.44 J8.7@2652.36,427.95
IO_D5: J8.6 R132.1 U1.43 | length 1338.9
  Top Layer w10: J8.6@2549.21,324.8 2607.11,382.7 2607.11,569.71 v1(2677.17,639.76) ; v1(3100.39,846.46) 3257.87,1003.94 U1.43@3433.07,1003.94
  Bottom Layer w10: R132.1@2483.46,327.95 J8.6@2547.64,327.95 ; v1(2677.17,639.76) 2755.91,639.76 2854.33,738.19 2992.13,738.19 v1(3100.39,846.46)
IO_D6: J8.5 R137.2 U1.48 | length 1194.3
  Top Layer w10: v1@3302.17,851.38 3356.3,905.51 U1.48@3433.07,905.51
  Bottom Layer w10: J8.5@2647.64,324.8 J8.5@2650.79,327.95 ; J8.5@2647.64,327.95 J8.5@2650.79,327.95 ; R137.2@2713.39,327.95 J8.5@2650.79,327.95 ; v1(3297.24,846.46) 3090.55,639.76 2913.39,639.76 2864.17,590.55 2864.17,403.54 2834.65,374.02 2696.85,374.02 J8.5@2650.79,327.95
IO_D7: J8.4 R133.1 U1.44 | length 1442.3
  Top Layer w10: v1(3139.76,846.46) 3277.56,984.25 U1.44@3433.07,984.25
  Bottom Layer w10: R133.1@2481.89,227.95 J8.4@2547.64,227.95 ; J8.4@2549.21,226.38 2588.58,265.75 2588.58,570.87 2627.95,610.24 2755.91,610.24 2864.17,718.5 3011.81,718.5 v1(3139.76,846.46)
IO_D8: J8.3 R138.2 U1.49 | length 1278.7
  Top Layer w10: v1@3341.54,851.38 3375.98,885.83 U1.49@3433.07,885.83
  Bottom Layer w10: J8.3@2647.64,226.38 J8.3@2649.21,227.95 ; J8.3@2647.64,227.95 J8.3@2649.21,227.95 ; R138.2@2724.8,227.95 J8.3@2649.21,227.95 ; v1(3336.61,846.46) 3110.24,620.08 2923.23,620.08 2883.86,580.71 2883.86,324.8 2834.65,275.59 2696.85,275.59 J8.3@2649.21,227.95
IO_D9: J8.2 R134.1 U1.45 | length 1516.8
  Top Layer w10: v1(3179.13,846.46) 3297.24,964.57 U1.45@3433.07,964.57
  Bottom Layer w10: R134.1@2480.32,127.95 J8.2@2547.64,127.95 ; J8.2@2549.21,127.95 2607.11,185.85 2607.11,559.87 2637.8,590.55 2765.75,590.55 2874.02,698.82 3031.5,698.82 v1(3179.13,846.46)
IO_D10: J8.1 R139.2 U1.50 | length 1350.4
  Top Layer w10: v1(3375.98,846.46) 3395.67,866.14 U1.50@3433.07,866.14
  Bottom Layer w10: R139.2@2716.54,127.95 J8.1@2647.64,127.95 2696.85,177.17 2834.65,177.17 2903.54,246.06 2903.54,570.87 2933.07,600.39 3129.92,600.39 v1(3375.98,846.46)
JTAG_TCK: J2.1 R3.1 U1.147 | length 2619.5
  Top Layer w10: v1(4625.98,1161.42) 4645.67,1181.1 U1.147@4795.28,1181.1
  Bottom Layer w10: R3.1@3145.67,19.68 3100.39,19.68 3051.18,68.9 J2.1@3051.18,147.64 3326.77,147.64 3395.67,216.54 3622.05,216.54 3838.58,433.07 3838.58,767.72 3937.01,866.14 4429.13,866.14 4625.98,1062.99 v1(4625.98,1161.42)
JTAG_TDI: J2.9 R2.1 U1.155 | length 2466.5
  Top Layer w10: v1(4537.4,1220.47) 4655.51,1338.58 U1.155@4795.28,1338.58
  Bottom Layer w10: J2.9@3051.18,547.64 3133.46,547.64 3212.6,468.5 R2.1@3212.6,423.23 3740.16,423.23 3779.53,462.6 3779.53,797.24 3907.48,925.2 4360.24,925.2 4537.4,1102.36 v1(4537.4,1220.47)
JTAG_TDO: J2.3 U1.149 | length 2412.3
  Top Layer w10: v1(4566.93,1200.79) 4586.61,1220.47 U1.149@4795.28,1220.47
  Bottom Layer w10: J2.3@3051.18,247.64 3098.82,295.28 3641.73,295.28 3799.21,452.76 3799.21,787.4 3917.32,905.51 4389.76,905.51 4566.93,1082.68 v1(4566.93,1200.79)
JTAG_TMS: J2.5 R1.1 U1.148 | length 2626.9
  Top Layer w10: v1(4596.46,1181.1) 4616.14,1200.79 U1.148@4795.28,1200.79
  Bottom Layer w10: J2.5@3051.18,347.64 3001.97,298.43 3001.97,226.38 3031.5,196.85 3080.71,196.85 3100.39,216.54 R1.1@3145.67,216.54 ; R1.1@3142.52,219.68 R1.1@3145.67,216.54 ; v1(4596.46,1181.1) 4596.46,1072.83 4409.45,885.83 3927.17,885.83 3818.9,777.56 3818.9,442.91 3631.89,255.91 3185.04,255.91 R1.1@3145.67,216.54
NCE: J3.6 R4.2 U1.33 | length 708.1
  Top Layer w10: v1(3346.46,1250) 3395.67,1200.79 U1.33@3433.07,1200.79
  Bottom Layer w10: R4.2@2858.27,1053.15 2858.27,1106.3 J3.6@2952.76,1200.79 ; J3.6@2951.18,1203.94 2997.24,1250 v1(3346.46,1250)
NCONFIG: J3.5 R7.2 U1.26 | length 529
  Top Layer w10: J3.5@3051.18,1203.94 3185.83,1338.58 U1.26@3433.07,1338.58
  Bottom Layer w10: J3.5@3051.18,1203.94 R7.2@3142.52,1203.94
NCSO: J3.8 U1.24 U2.1 | length 1057.5
  Top Layer w10: U2.1@2515.75,1039.57 2535.63,1039.57 2800,1303.94 J3.8@2951.18,1303.94 2995.67,1348.43 3070.87,1348.43 3100.39,1377.95 U1.24@3433.07,1377.95
NetC61_1: C61.1 R81.1 | length 70.9
  Bottom Layer w10: C61.1@3005.91,2962.6 R81.1@3076.77,2962.6
NetC61_2: C61.2 D1.1 U9.2 U25.12 | length 663.7
  Top Layer w10: U9.2@2936.22,3187.4 2987.01,3238.19 3297.24,3238.19 U25.12@3336.61,3277.56
  Bottom Layer w10: U9.2@2936.22,3187.4 2938.98,3184.65 C61.2@2938.98,2962.6
NetC62_1: C62.1 R82.1 | length 70.9
  Bottom Layer w10: C62.1@2661.42,2962.6 R82.1@2732.28,2962.6
NetC62_2: C62.2 D2.1 U10.2 U25.13 | length 1025.2
  Top Layer w10: U10.2@2591.73,3187.4 2636.9,3142.24 3250.5,3142.24 U25.13@3336.61,3228.35
  Bottom Layer w10: U10.2@2591.73,3187.4 2594.49,3184.65 C62.2@2594.49,2962.6
NetC63_1: C63.1 R83.1 | length 70.9
  Bottom Layer w10: C63.1@2307.09,2962.6 R83.1@2377.95,2962.6
NetC63_2: C63.2 D3.1 U11.2 U25.14 | length 1372.4
  Top Layer w10: U11.2@2237.4,3187.4 2298.57,3126.24 3283.72,3126.24 U25.14@3336.61,3179.13
  Bottom Layer w10: U11.2@2237.4,3187.4 2240.16,3184.65 C63.2@2240.16,2962.6
NetC64_1: C64.1 R84.1 | length 70.9
  Bottom Layer w10: C64.1@1962.6,2962.6 R84.1@2033.46,2962.6
NetC64_2: C64.2 D4.1 U12.2 U25.15 | length 1713.6
  Top Layer w10: U12.2@1889.76,3188.98 1968.5,3110.24 3316.93,3110.24 U25.15@3336.61,3129.92
  Bottom Layer w10: U12.2@1892.91,3187.4 1895.67,3184.65 C64.2@1895.67,2962.6
NetC65_1: C65.1 R85.1 | length 70.9
  Bottom Layer w10: C65.1@1618.11,2962.6 R85.1@1688.98,2962.6
NetC65_2: C65.2 D5.1 U13.2 U25.16 | length 2062.1
  Top Layer w10: U13.2@1545.28,3188.98 1653.54,3080.71 U25.16@3336.61,3080.71
  Bottom Layer w10: U13.2@1548.43,3187.4 1551.18,3184.65 C65.2@1551.18,2962.6
NetC66_1: C66.1 R86.1 | length 70.9
  Bottom Layer w10: C66.1@1273.62,2962.6 R86.1@1344.49,2962.6
NetC66_2: C66.2 D6.1 U14.2 U25.17 | length 2427
  Top Layer w10: U14.2@1200.79,3188.98 1358.27,3031.5 U25.17@3336.61,3031.5
  Bottom Layer w10: U14.2@1203.94,3187.4 1206.69,3184.65 C66.2@1206.69,2962.6
NetC67_1: C67.1 R87.1 | length 70.9
  Bottom Layer w10: C67.1@929.13,2962.6 R87.1@1000,2962.6
NetC67_2: C67.2 D7.1 U15.2 U25.18 | length 2791.9
  Top Layer w10: U15.2@856.3,3188.98 1062.99,2982.28 U25.18@3336.61,2982.28
  Bottom Layer w10: U15.2@859.45,3187.4 862.2,3184.65 C67.2@862.2,2962.6
NetC68_1: C68.1 R88.1 | length 70.9
  Bottom Layer w10: C68.1@584.65,2962.6 R88.1@655.51,2962.6
NetC68_2: C68.2 D8.1 U16.2 U25.19 | length 3196.1
  Top Layer w10: U16.2@511.81,3188.98 767.72,2933.07 U25.19@3375.98,2933.07
  Bottom Layer w10: U16.2@514.96,3187.4 517.72,3184.65 C68.2@517.72,2962.6
NetC71_1: C71.1 R91.1 | length 70.9
  Bottom Layer w10: C71.1@2996.06,2312.99 R91.1@3066.93,2312.99
NetC71_2: C71.2 D11.1 U17.2 U26.12 | length 673.5
  Top Layer w10: U17.2@2926.38,2537.8 2977.17,2588.58 3297.24,2588.58 U26.12@3336.61,2627.95
  Bottom Layer w10: U17.2@2926.38,2537.8 2929.13,2535.04 C71.2@2929.13,2312.99
NetC72_1: C72.1 R92.1 | length 70.9
  Bottom Layer w10: C72.1@2651.57,2312.99 R92.1@2722.44,2312.99
NetC72_2: C72.2 D12.1 U18.2 U26.13 | length 1060.6
  Top Layer w10: U18.2@2578.74,2539.37 2627.95,2490.16 3248.03,2490.16 3336.61,2578.74 U26.13@3356.3,2578.74
  Bottom Layer w10: U18.2@2581.89,2537.8 2584.65,2535.04 C72.2@2584.65,2312.99
NetC73_1: C73.1 R93.1 | length 70.9
  Bottom Layer w10: C73.1@2307.09,2312.99 R93.1@2377.95,2312.99
NetC73_2: C73.2 D13.1 U19.2 U26.14 | length 1381.3
  Top Layer w10: U19.2@2234.25,2539.37 2303.15,2470.47 3277.56,2470.47 U26.14@3336.61,2529.53
  Bottom Layer w10: U19.2@2237.4,2537.8 2240.16,2535.04 C73.2@2240.16,2312.99
NetC74_1: C74.1 R94.1 | length 70.9
  Bottom Layer w10: C74.1@1962.6,2312.99 R94.1@2033.46,2312.99
NetC74_2: C74.2 D14.1 U20.2 U26.15 | length 1717.9
  Top Layer w10: U20.2@1892.91,2537.8 1979.92,2450.79 3307.09,2450.79 U26.15@3336.61,2480.32
  Bottom Layer w10: U20.2@1892.91,2537.8 1895.67,2535.04 C74.2@1895.67,2312.99
NetC75_1: C75.1 R95.1 | length 82.3
  Bottom Layer w10: C75.1@1627.95,2322.83 R95.1@1698.82,2322.83 1702.76,2326.77 R95.1@1702.76,2332.68
NetC75_2: C75.2 D15.1 U21.2 U26.16 | length 2028.5
  Top Layer w10: U21.2@1564.96,2529.53 1663.39,2431.1 U26.16@3336.61,2431.1
  Bottom Layer w10: U21.2@1558.27,2537.8 1561.02,2535.04 C75.2@1561.02,2322.83
NetC76_1: C76.1 R96.1 | length 70.9
  Bottom Layer w10: C76.1@1273.62,2322.83 R96.1@1344.49,2322.83
NetC76_2: C76.2 D16.1 U22.2 U26.17 | length 2417.2
  Top Layer w10: U22.2@1200.79,2539.37 1358.27,2381.89 U26.17@3336.61,2381.89
  Bottom Layer w10: U22.2@1203.94,2537.8 1206.69,2535.04 C76.2@1206.69,2322.83
NetC77_1: C77.1 R97.1 | length 70.9
  Bottom Layer w10: C77.1@929.13,2322.83 R97.1@1000,2322.83
NetC77_2: C77.2 D17.1 U23.2 U26.18 | length 2821.4
  Top Layer w10: U23.2@856.3,2539.37 1062.99,2332.68 U26.18@3375.98,2332.68
  Bottom Layer w10: U23.2@859.45,2537.8 862.2,2535.04 C77.2@862.2,2322.83
NetC78_1: C78.1 R98.1 | length 74.8
  Bottom Layer w10: C78.1@584.65,2322.83 R98.1@655.51,2322.83 R98.1@659.45,2322.83
NetC78_2: C78.2 D18.1 U24.2 U26.19 | length 3181.6
  Top Layer w10: U24.2@511.81,2539.37 767.72,2283.46 U26.19@3371.26,2283.46
  Bottom Layer w10: U24.2@514.96,2537.8 517.72,2535.04 C78.2@517.72,2322.83
NetC81_1: C81.1 Q1.2 R100.2 | length 168.4
  Top Layer w10: v1(5078.74,2214.57) Q1.2@5078.74,2258.93
  Bottom Layer w10: v1(5078.74,2214.57) C81.1@5078.74,2259.84 R100.2@5157.48,2259.84
NetC82_1: C82.1 Q2.2 R102.2 | length 156.2
  Top Layer w10: v1(5078.74,2549.21) Q2.2@5078.74,2588.58
  Bottom Layer w10: v1(5078.74,2549.21) 5078.74,2587.78 5155.76,2587.78 R102.2@5156.62,2588.64
NetC83_1: C83.1 Q3.2 R104.2 | length 169.6
  Top Layer w10: v1(4822.83,2214.57) 4822.83,2258.93 Q3.2@4823.69,2259.79
  Bottom Layer w10: v1(4822.83,2214.57) C83.1@4822.83,2259.84 R104.2@4901.57,2259.84
NetC84_1: C84.1 Q4.2 R106.2 | length 169.6
  Top Layer w10: v1(4822.83,2549.21) 4822.83,2593.57 Q4.2@4823.69,2594.43
  Bottom Layer w10: v1(4822.83,2549.21) C84.1@4822.83,2594.49 R106.2@4901.57,2594.49
NetC85_1: C85.1 Q5.2 R108.2 | length 169.6
  Top Layer w10: v1(4576.77,2214.57) 4576.77,2258.93 Q5.2@4577.63,2259.79
  Bottom Layer w10: v1(4576.77,2214.57) C85.1@4576.77,2259.84 R108.2@4655.51,2259.84
NetC86_1: C86.1 Q6.2 R110.2 | length 169.6
  Top Layer w10: v1(4576.77,2549.21) 4576.77,2593.57 Q6.2@4577.63,2594.43
  Bottom Layer w10: v1(4576.77,2549.21) C86.1@4576.77,2594.49 R110.2@4655.51,2594.49
NetC87_1: C87.1 Q7.2 R112.2 | length 169.6
  Top Layer w10: v1(4311.02,2214.57) 4311.02,2258.93 Q7.2@4311.88,2259.79
  Bottom Layer w10: v1(4311.02,2214.57) C87.1@4311.02,2259.84 R112.2@4389.76,2259.84
NetC88_1: C88.1 Q8.2 R114.2 | length 169.6
  Top Layer w10: v1(4311.02,2549.21) 4311.02,2593.57 Q8.2@4311.88,2594.43
  Bottom Layer w10: v1(4311.02,2549.21) C88.1@4311.02,2594.49 R114.2@4389.76,2594.49
NetJ4_d2: J4.D2 J4.E2 | length 78.7
  Top Layer w6: J4.E2@5784.65,17.72 J4.D2@5863.39,17.72
NetLED1_1: LED1.1 U1.68 | length 606.5
  Top Layer w6: U1.68@3671.26,568.9 3671.26,510.39 4043.85,137.8 LED1.1@4064.96,137.8
NetLED1_2: LED1.2 R120.1 | length 82.7
  Top Layer w12: v1(4064.96,29.53) LED1.2@4064.96,70.87
  Bottom Layer w10: v1(4064.96,29.53) R120.1@4064.96,70.87
NetLED2_1: LED2.1 U1.67 | length 565.6
  Top Layer w6: U1.67@3651.57,568.9 3651.57,462.6 LED2.1@3976.38,137.8
NetLED2_2: LED2.2 R121.1 | length 82.7
  Top Layer w12: v1(3976.38,29.53) LED2.2@3976.38,70.87
  Bottom Layer w10: v1(3976.38,29.53) R121.1@3976.38,70.87
NetLED3_1: LED3.1 U1.66 | length 537.1
  Top Layer w6: U1.66@3631.89,568.9 3631.89,393.7 LED3.1@3887.8,137.8
NetLED3_2: LED3.2 R122.1 | length 82.7
  Top Layer w12: v1(3887.8,29.53) LED3.2@3887.8,70.87
  Bottom Layer w10: v1(3887.8,29.53) R122.1@3887.8,70.87
NetLED4_1: LED4.1 U1.65 | length 508.6
  Top Layer w6: U1.65@3612.2,568.9 3612.2,324.8 LED4.1@3799.21,137.8
NetLED4_2: LED4.2 R123.1 | length 82.7
  Top Layer w12: v1(3799.21,29.53) LED4.2@3799.21,70.87
  Bottom Layer w10: v1(3799.21,29.53) R123.1@3799.21,70.87
NetLED5_1: LED5.1 U1.64 | length 480
  Top Layer w6: U1.64@3592.52,568.9 3592.52,255.91 LED5.1@3710.63,137.8
NetLED5_2: LED5.2 R124.1 | length 82.7
  Top Layer w12: v1(3710.63,29.53) LED5.2@3710.63,70.87
  Bottom Layer w10: v1(3710.63,29.53) R124.1@3710.63,70.87
NetLED6_1: LED6.1 U1.63 | length 451.5
  Top Layer w6: U1.63@3572.83,568.9 3572.83,187.01 LED6.1@3622.05,137.8
NetLED6_2: LED6.2 R125.1 | length 82.7
  Top Layer w12: v1(3622.05,29.53) LED6.2@3622.05,70.87
  Bottom Layer w10: v1(3622.05,29.53) R125.1@3622.05,70.87
NetLED7_1: LED7.1 U1.62 | length 439.3
  Top Layer w6: LED7.1@3533.46,137.8 3553.15,157.48 U1.62@3553.15,568.9
NetLED7_2: LED7.2 R126.1 | length 82.7
  Top Layer w10: v1(3533.46,29.53) LED7.2@3533.46,70.87
  Bottom Layer w10: v1(3533.46,29.53) R126.1@3533.46,70.87
NetLED8_1: LED8.1 U1.61 | length 467.8
  Top Layer w6: LED8.1@3444.88,137.8 3533.46,226.38 U1.61@3533.46,568.9
NetLED8_2: LED8.2 R127.1 | length 82.7
  Top Layer w10: v1(3444.88,29.53) LED8.2@3444.88,70.87
  Bottom Layer w10: v1(3444.88,29.53) R127.1@3444.88,70.87
NetLED9_2: LED9.2 R200.2 | length 78.7
  Top Layer w10: R200.2@4547.24,3440.94 LED9.2@4625.98,3440.94
NetQ1_1: Q1.1 R101.1 | length 105.4
  Top Layer w10: Q1.1@5117,2358.21 5117,2361.09 v1(5157.48,2401.57)
  Bottom Layer w10: R101.1@5112.2,2401.57 v1(5157.48,2401.57)
NetQ2_1: Q2.1 R103.1 | length 105.4
  Top Layer w10: Q2.1@5116.14,2687.01 5116.14,2689.89 v1(5156.62,2730.37)
  Bottom Layer w10: R103.1@5111.35,2730.37 v1(5156.62,2730.37)
NetQ3_1: Q3.1 R105.1 | length 105.4
  Top Layer w10: Q3.1@4861.09,2358.21 4861.09,2361.09 v1(4901.57,2401.57)
  Bottom Layer w10: R105.1@4856.3,2401.57 v1(4901.57,2401.57)
NetQ4_1: Q4.1 R107.1 | length 105.4
  Top Layer w10: Q4.1@4861.09,2692.86 4861.09,2695.74 v1(4901.57,2736.22)
  Bottom Layer w10: R107.1@4856.3,2736.22 v1(4901.57,2736.22)
NetQ5_1: Q5.1 R109.1 | length 105.4
  Top Layer w10: Q5.1@4615.03,2358.21 4615.03,2361.09 v1(4655.51,2401.57)
  Bottom Layer w10: R109.1@4610.24,2401.57 v1(4655.51,2401.57)
NetQ6_1: Q6.1 R111.1 | length 105.4
  Top Layer w10: Q6.1@4615.03,2692.86 4615.03,2695.74 v1(4655.51,2736.22)
  Bottom Layer w10: R111.1@4610.24,2736.22 v1(4655.51,2736.22)
NetQ7_1: Q7.1 R113.1 | length 101
  Top Layer w10: Q7.1@4350.39,2362.2 v1(4389.76,2401.57)
  Bottom Layer w10: R113.1@4344.49,2401.57 v1(4389.76,2401.57)
NetQ8_1: Q8.1 R115.1 | length 105.4
  Top Layer w10: Q8.1@4349.28,2692.86 4349.28,2695.74 v1(4389.76,2736.22)
  Bottom Layer w10: R115.1@4344.49,2736.22 v1(4389.76,2736.22)
NetR9_1: R9.1 U1.34 | length 440.1
  Top Layer w10: v1(3287.4,1309.06) 3287.4,1230.32 3336.61,1181.1 U1.34@3433.07,1181.1
  Bottom Layer w10: R9.1@3212.6,1446.85 3257.87,1446.85 3287.4,1417.32 v1(3287.4,1309.06)
NetR10_1: R10.1 U1.35 | length 383.9
  Top Layer w10: v1(3257.87,1279.53) 3257.87,1230.32 3326.77,1161.42 U1.35@3433.07,1161.42
  Bottom Layer w10: R10.1@3198.82,1377.95 R10.1@3212.6,1377.95 3212.6,1324.8 v1(3257.87,1279.53)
